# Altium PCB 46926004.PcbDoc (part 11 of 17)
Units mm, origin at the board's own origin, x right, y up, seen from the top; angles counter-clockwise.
Board outline 250 x 200 mm, 6 copper layers (Top Layer, INT1_GND, INT2_SIG, INT3_SIG, INT4_GND, Bottom Layer), stack 1.71 mm thick; 1450 components, 1293 nets, 5656 pads, 2307 vias.
Unrouted connection lines stored in the file: 2.
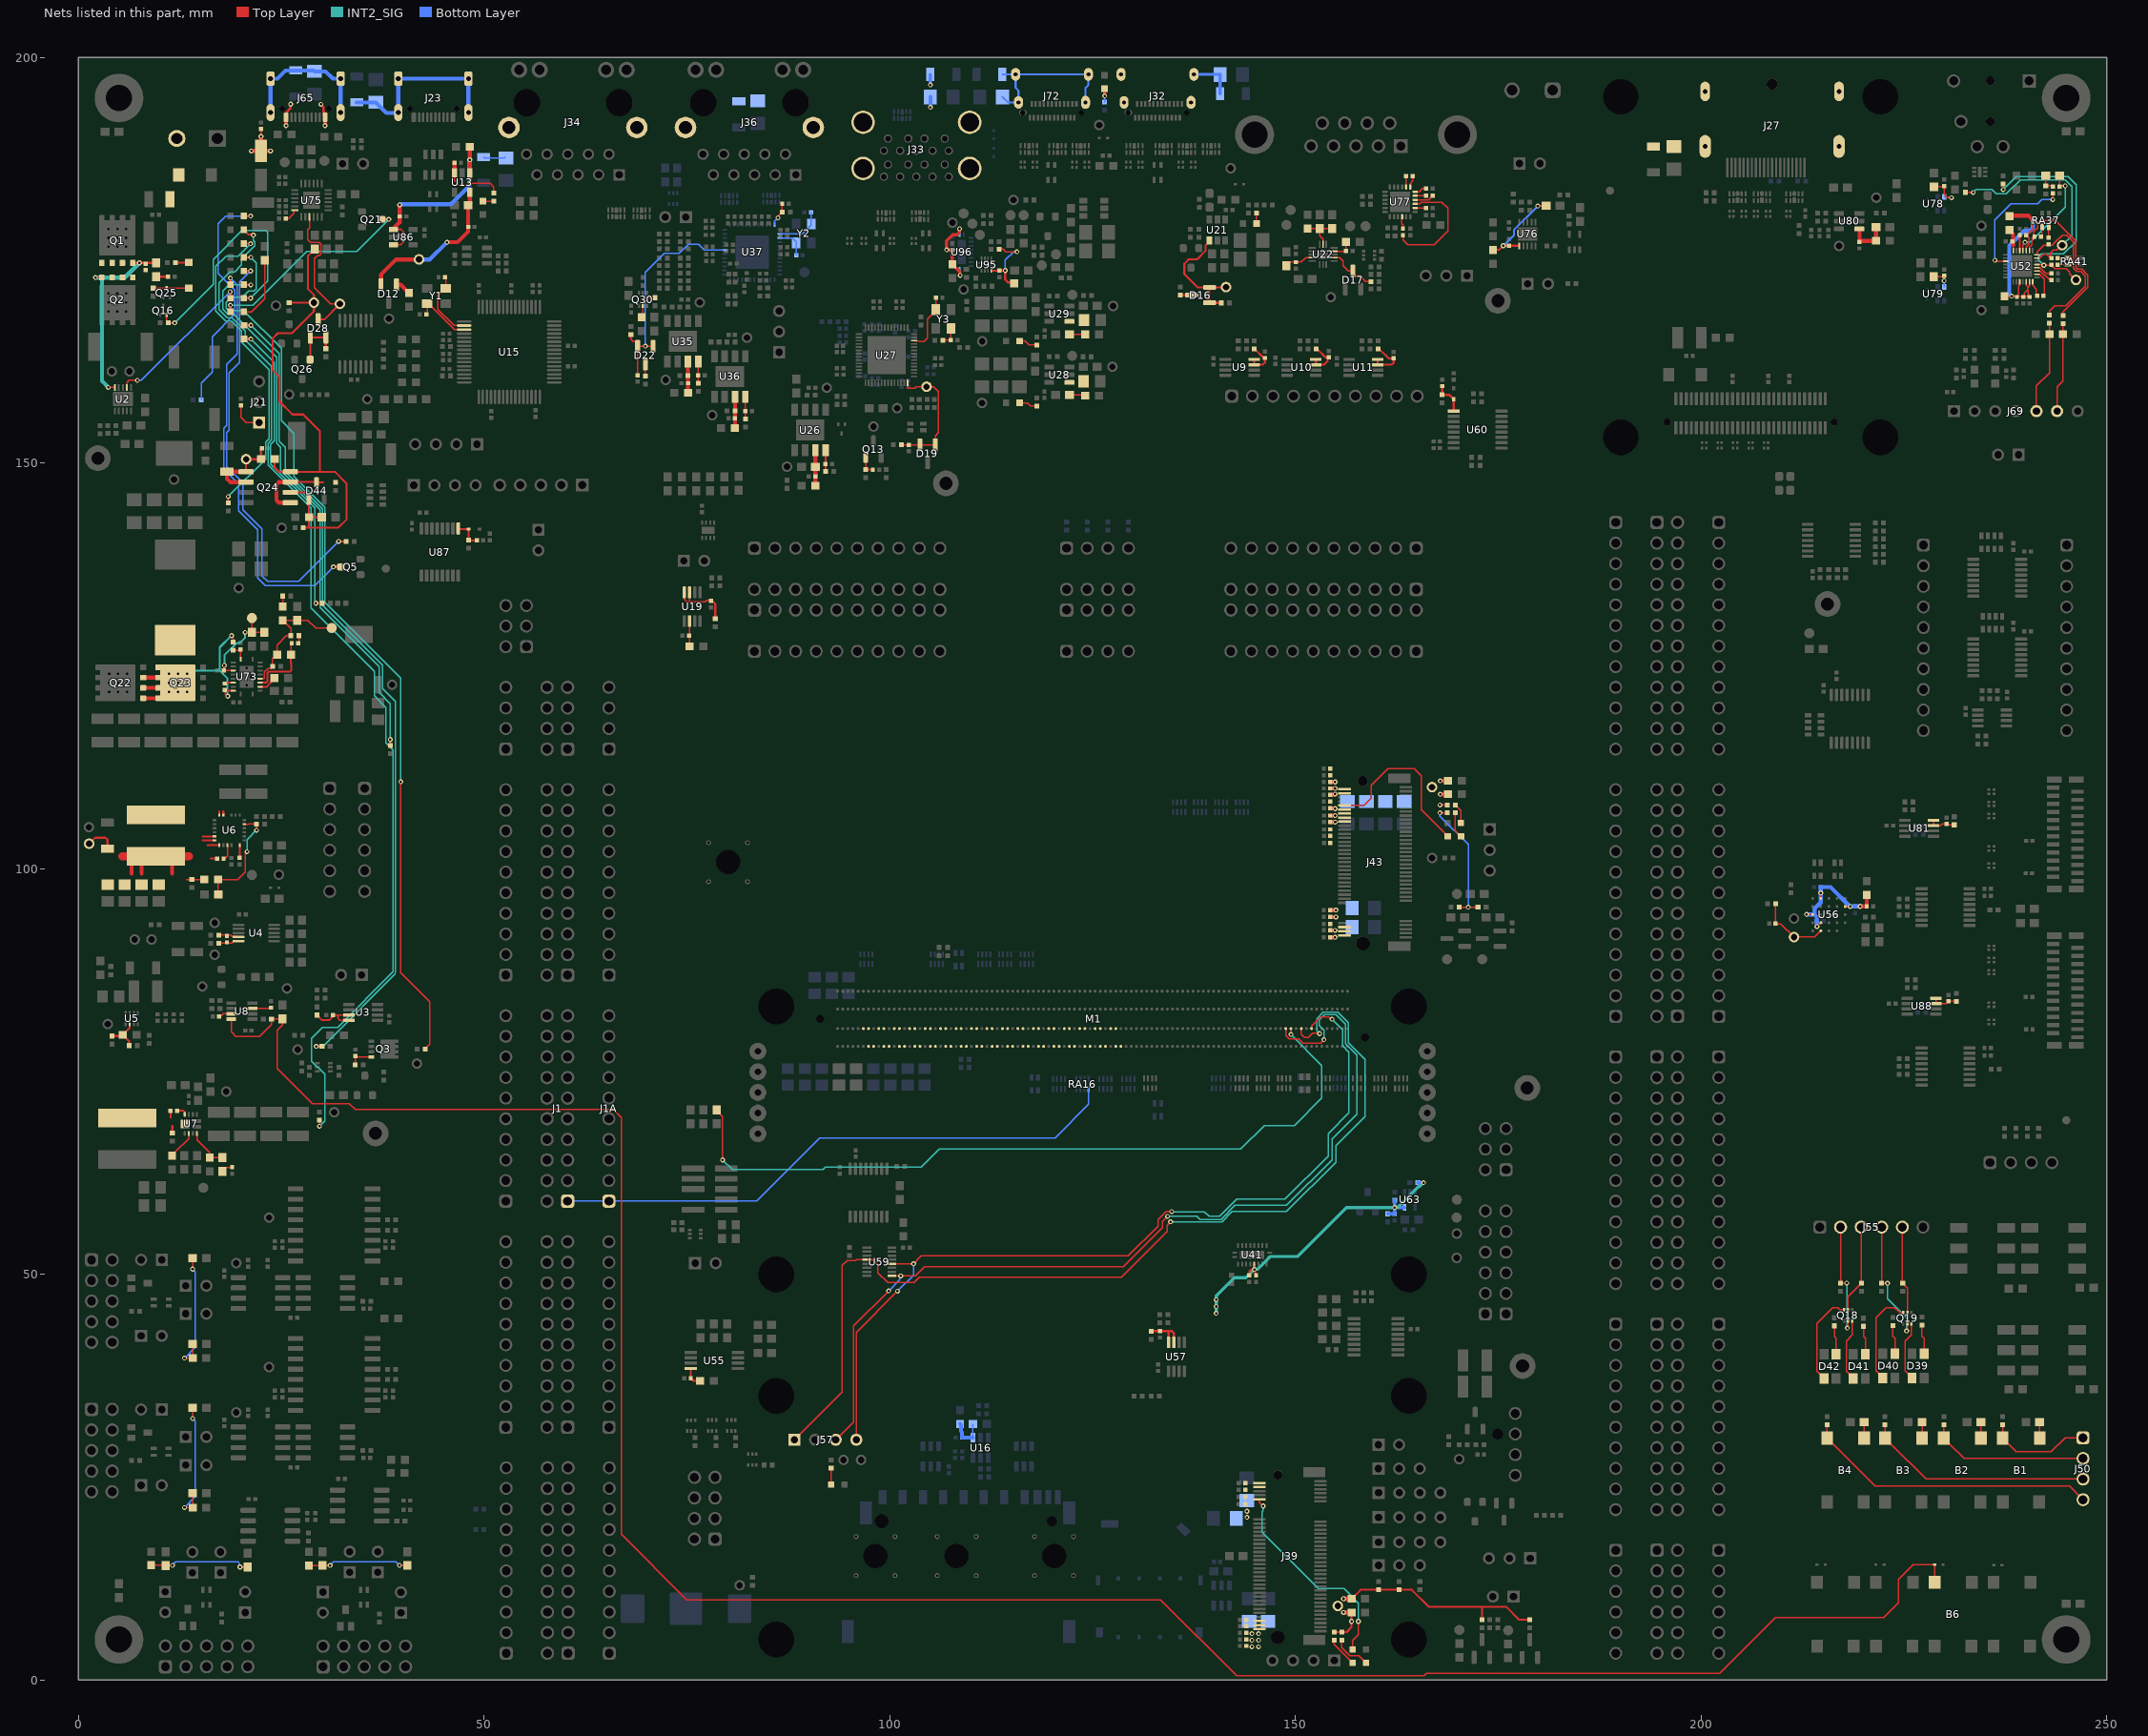
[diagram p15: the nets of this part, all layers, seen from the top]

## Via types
v1: diameter 0.6, hole 0.3, Top Layer to Bottom Layer, tented both sides, 2171 vias
v2: diameter 0.6, hole 0.3, Top Layer to Bottom Layer, 48 vias
v3: diameter 1, hole 0.5, Top Layer to Bottom Layer, tented both sides, 37 vias
v4: diameter 0.5, hole 0.2, Top Layer to Bottom Layer, tented both sides, 34 vias
v5: diameter 0.6, hole 0.3, Top Layer to Bottom Layer, tented bottom, 17 vias

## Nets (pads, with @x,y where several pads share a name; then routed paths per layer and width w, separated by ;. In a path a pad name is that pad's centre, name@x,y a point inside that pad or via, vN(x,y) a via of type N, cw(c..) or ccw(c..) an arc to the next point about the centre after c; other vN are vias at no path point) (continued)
JTAG_1_TDI: J57.4 M1.C08 U59.12 | length 107.1
  Top Layer w0.15: J57.4@95.88,29.62 95.88,42.841 v1(100.958,47.919) ; U59.12@100.263,51.3 100.269,51.306 102.932,51.306 v1(102.939,51.313) 103.898,52.272 129.389,52.272 133.063,55.946 133.063,56.758 134.052,57.748 v1(134.752,57.748) ; M1.C08@151.987,80.3 151.987,80.636 153.104,81.753 154.092,81.753 154.392,81.453 v1(154.514,81.453)
  INT2_SIG w0.15: v1(134.752,57.748) 134.787,57.712 138.788,57.712 139.346,57.154 140.654,57.154 142.785,59.285 148.732,59.285 154.034,64.587 154.034,67.324 156.6,69.89 156.6,77.4 155.797,78.203 155.797,80.17 v1(154.514,81.453)
  Bottom Layer w0.15: v1(100.958,47.919) 102.939,49.9 v1(102.939,51.313)
JTAG_1_TDO: J57.1 M1.C10 U59.4 | length 123
  Top Layer w0.15: J57.1@88.26,29.62 94.143,35.503 94.143,51.105 94.743,51.704 95.81,51.704 95.905,51.8 U59.4@97.187,51.8 97.914,51.8 98.535,51.179 98.535,50.204 99.738,49 103,49 103.65,49.65 128.581,49.65 134.195,55.264 134.195,56.071 v1(134.602,56.477) ; M1.C10@150.717,80.3 150.717,79.618 151.11,79.225 151.585,79.225 152.109,79.749 152.91,79.749 v1(152.989,79.67)
  INT2_SIG w0.15: v1(134.602,56.477) 140.932,56.477 142.202,57.748 148.898,57.748 154.982,63.832 154.982,65.891 158.56,69.469 158.56,76.482 156.5,78.542 156.5,81.017 155.217,82.3 153.434,82.3 152.635,81.501 152.635,80.024 v1(152.989,79.67)
JTAG_1_TMS: J57.3 M1.C13 U59.9 | length 115.8
  Top Layer w0.15: J57.3@93.34,29.62 95.533,31.812 95.533,43.629 v1(99.864,47.961) ; U59.9@100.263,49.8 v1(101.347,49.8) 103.155,49.8 104.305,50.95 128.793,50.95 133.63,55.787 133.63,56.526 v1(134.247,57.142) ; M1.C13@148.812,80.3 148.812,79.451 149.01,79.253 149.014,79.253 149.23,79.038 150.425,79.038 150.938,78.524 153.099,78.524 v1(153.5,78.925)
  INT2_SIG w0.15: v1(134.247,57.142) 137.862,57.142 138.227,56.777 140.808,56.777 142.53,58.5 148.894,58.5 154.514,64.119 154.514,66.66 157.6,69.746 157.6,77.018 156.159,78.459 156.159,80.83 154.989,82 153.558,82 152.935,81.377 152.935,80.659 153.514,80.08 153.514,78.939 v1(153.5,78.925)
  Bottom Layer w0.15: v1(99.864,47.961) 101.261,49.357 101.261,49.714 v1(101.347,49.8)
JTAG_1_VREF: M1.C12 R287.2 | length 94.6
  Top Layer w0.15: R287.2@78.65,70.25 78.65,70.2 79.375,69.475 79.375,64.11 v1(79.385,64.1) ; v1(149.447,79.563) M1.C12@149.447,80.3
  INT2_SIG w0.15: v1(79.385,64.1) 80.585,62.9 91.75,62.9 92.05,63.2 103.889,63.2 106.138,65.449 143.267,65.449 146.153,68.336 149.86,68.336 153.247,71.722 153.247,75.333 153.247,75.763 v1(149.447,79.563)
LED1: J55.5 Q19.2 R275.2 | length 10.8
  Top Layer w0.15: J55.5@224.805,55.825 224.805,48.945 R275.2@224.85,48.9 225.425,48.325 Q19.2@225.425,45.275
LED2: J55.4 Q19.5 R276.2 | length 15.4
  Top Layer w0.15: J55.4@222.265,55.825 222.265,48.915 R276.2@222.25,48.9 v1(222.975,48.9) ; v1(225.328,43.026) 225.328,43.147 225.425,43.245 Q19.5@225.425,43.925
  INT2_SIG w0.15: v1(222.975,48.9) 222.975,47 225.328,44.647 v1(225.328,43.026)
LED3: J55.3 Q18.2 R277.2 | length 10.9
  Top Layer w0.15: Q18.2@218.11,45.625 218.11,47.26 R277.2@219.75,48.9 219.725,48.925 J55.3@219.725,55.825
LED4: J55.2 Q18.5 R278.2 | length 14.2
  Top Layer w0.15: J55.2@217.185,55.825 217.185,48.915 R278.2@217.2,48.9 217.225,48.925 v1(217.95,48.925) ; v1(218.013,43.376) 218.013,43.497 218.11,43.595 Q18.5@218.11,44.275
  INT2_SIG w0.15: v1(217.95,48.925) 217.981,48.894 217.981,43.407 v1(218.013,43.376)
LINEOUTL: C333.2 L43.1 U52.16 | length 18.6
  Top Layer w0.15: U52.16@241.396,175.675 241.396,176.021 242.25,176.875 243.271,176.875 243.586,177.189 243.589,177.192 244.521,178.075 ; L43.1@242.925,168.225 242.925,168.75 243.575,169.4 244.951,169.4 247.35,171.799 247.35,173.05 246.8,173.6 246.293,173.6 245.885,174.008 245.885,177.24 245.05,178.075 244.521,178.075
LINEOUTL_CONN: C341.2 J69.5 L43.2 | length 11.5
  Top Layer w0.15: J69.5@241.33,156.4 241.33,159.505 242.925,161.1 C341.2@242.925,165.9 L43.2@242.925,167.225
LINEOUTR: C326.2 L45.1 U52.18 | length 21.1
  Top Layer w0.15: U52.18@240.471,176.2 240.481,176.21 240.481,176.619 240.775,176.913 240.775,177.75 240.95,177.925 241,177.925 241,178.526 241.45,178.976 241.45,179.55 241.825,179.925 243.624,179.925 246.185,177.364 246.185,174.132 246.417,173.9 246.924,173.9 247.65,173.174 247.65,171.675 244.6,168.625 L45.1@244.6,168.175
LINEOUTR_CONN: C338.2 J69.6 L45.2 | length 11.1
  Top Layer w0.15: J69.6@243.87,156.4 243.87,159.395 244.6,160.125 C338.2@244.6,165.9 L45.2@244.6,167.175
M2B_3V3: C192.2 C193.2 C194.2 C195.2 C196.1 C286.1 C358.2 C361.2 C362.2 C363.2 C364.2 C365.2 C366.2 C367.2 C368.2 C369.2 J39.2 J39.4 J39.70 J39.72 J39.74 L46.2 L47.2 R181.2 R184.1 R186.2 R187.2 R188.2 R195.1 R196.2 R197.2 R322.1 U41.6 U63.5 X63.1 | length 72.3
  Top Layer w0.25: C286.1@144.321,49.885 144.321,50.383 144.502,50.564 144.762,50.564 144.795,50.598 v1(144.923,50.598) ; U41.6@144.923,51.25 v1(144.923,50.598) ; C196.1@145.156,49.885 145.021,50.02 145.021,50.405 144.923,50.503 v1(144.923,50.598) ; R197.2@154.78,5.905 156.308,5.905 156.906,6.503 v1(156.906,7.222) L46.2@156.906,8.322 L46.2@156.904,8.319 ; L47.2@156.906,10.022 156.931,10.022 158.035,11.125 R196.2@160.25,11.125 R195.1@162.79,11.125 164.33,11.125 166.417,9.038 172.987,9.038 ; R184.1@172.987,7.423 172.987,9.038 ; R322.1@178.9,7.428 177.562,7.428 175.952,9.038 172.987,9.038
  Top Layer w0.6: v1(155.934,8.319) L46.2@156.904,8.319 ; v1(155.934,10.019) L47.2@156.904,10.019
  INT2_SIG w0.4: v1(140.228,45.2) v1(140.228,46.033) v1(140.228,46.867) v1(140.228,46.867) 140.229,47.339 142.475,49.585 143.911,49.585 144.962,50.636 145.338,50.636 146.902,52.2 150.25,52.2 156.298,58.248 v1(162.231,58.248) 162.269,58.286 162.629,58.286 165.141,60.798 165.25,60.798 165.739,61.287 v1(165.794,61.287)
  Bottom Layer w0.4: R186.2@161.364,57.459 C358.2@162.232,57.459 v1(162.231,58.248) v1(162.231,58.248) ; R181.2@162.231,59.148 v1(162.231,58.248) ; U63.5@163.45,58.248 v1(162.231,58.248) ; R188.2@165.1,61.321 165.117,61.304 165.777,61.304 v1(165.794,61.287)
  other v1: 144.637,4.09 145.452,4.089 144.638,4.905 145.453,4.904 144.639,5.72 145.454,5.719 144.017,20.05 144.017,20.8
M2M_3V3: C200.2 C201.2 C202.2 C203.2 C370.2 C371.2 C372.2 C373.2 C374.2 C375.2 C376.2 C377.2 C378.2 C379.2 C380.2 C381.2 C382.2 C383.2 C384.2 C385.2 C386.2 C387.2 C388.2 J43.2 J43.4 J43.12 J43.14 J43.16 J43.18 J43.70 J43.72 J43.74 L48.2 L49.2 R200.2 R202.2 R204.2 R417.1 X68.1 | length 25.4
  Top Layer w0.15: v1(167.816,106.9) R204.2@168.7,106.9 ; v1(167.816,107.862) R202.2@168.694,107.862 ; R417.1@170.166,95.27 170.171,95.265 v1(171.298,95.265) 172.491,95.265 R200.2@172.496,95.27
  Top Layer w0.5: C377.2@154.293,94.049 v1(154.989,94.049) ; C375.2@154.293,94.896 v1(154.989,94.896) ; C202.2@154.293,109.084 154.303,109.094 154.767,109.094 154.875,109.201 v1(154.902,109.201) ; C201.2@154.293,109.9 v1(154.896,109.9) ; C200.2@154.293,110.693 v1(154.896,110.693) ; C382.2@154.297,91.55 v1(154.9,91.55) ; C381.2@154.297,92.4 v1(154.9,92.4) ; C387.2@154.3,105.75 v1(154.903,105.75) ; C386.2@154.3,106.55 v1(154.903,106.55) ; C385.2@154.3,107.45 154.31,107.44 154.836,107.44 154.869,107.408 v1(154.896,107.408) ; v1(167.853,109.179) L48.2@168.828,109.179 ; v1(167.853,110.829) L49.2@168.828,110.829
  Bottom Layer w0.15: v1(167.816,106.9) 167.816,106.459 171.298,102.977 v1(171.298,95.265)
MSP_1_RX_N: M1.C47
MSP_1_RX_P: M1.C46
MSP_1_TX_N: M1.D46
MSP_1_TX_P: M1.D45
MSP_2_RX_N: M1.C50
MSP_2_RX_P: M1.C49
MSP_2_TX_N: M1.D49
MSP_2_TX_P: M1.D48
MSP_3_RX_N: M1.C53
MSP_3_RX_P: M1.C52
MSP_3_TX_N: M1.D52
MSP_3_TX_P: M1.D51
MSP_4_RX_N: M1.C56
MSP_4_RX_P: M1.C55
MSP_4_TX_N: M1.D55
MSP_4_TX_P: M1.D54
MSP_5_RX_N: M1.C59
MSP_5_RX_P: M1.C58
MSP_5_TX_N: M1.D58
MSP_5_TX_P: M1.D57
MSP_6_RX_N: M1.C62
MSP_6_RX_P: M1.C61
MSP_6_TX_N: M1.D61
MSP_6_TX_P: M1.D60
MSP_7_RX_N: M1.C65
MSP_7_RX_P: M1.C64
MSP_7_TX_N: M1.D64
MSP_7_TX_P: M1.D63
MSP_8_RX_N: M1.C68
MSP_8_RX_P: M1.C67
MSP_8_TX_N: M1.D67
MSP_8_TX_P: M1.D66
MSP_9_RX_N: M1.C71
MSP_9_RX_P: M1.C70
MSP_9_TX_N: M1.D70
MSP_9_TX_P: M1.D69
MSP_10_RX_N: M1.C74
MSP_10_RX_P: M1.C73
MSP_10_TX_N: M1.D73
MSP_10_TX_P: M1.D72
MSP_11_RX_N: M1.C77
MSP_11_RX_P: M1.C76
MSP_11_TX_N: M1.D76
MSP_11_TX_P: M1.D75
MSP_12_RX_N: M1.C80
MSP_12_RX_P: M1.C79
MSP_12_TX_N: M1.D79
MSP_12_TX_P: M1.D78
MSP_13_RX_N: M1.C83
MSP_13_RX_P: M1.C82
MSP_13_TX_N: M1.D82
MSP_13_TX_P: M1.D81
MSP_14_RX_N: M1.C86
MSP_14_RX_P: M1.C85
MSP_14_TX_N: M1.D85
MSP_14_TX_P: M1.D84
MSP_15_RX_N: M1.C89
MSP_15_RX_P: M1.C88
MSP_15_TX_N: M1.D88
MSP_15_TX_P: M1.D87
MSP_16_RX_N: M1.C92
MSP_16_RX_P: M1.C91
MSP_16_TX_N: M1.D91
MSP_16_TX_P: M1.D90
MSP_17_RX_N: M1.C95
MSP_17_RX_P: M1.C94
MSP_17_TX_N: M1.D94
MSP_17_TX_P: M1.D93
NetB1_1: B1.1 R240.2 | length 2
  Top Layer w0.15: B1.1@241.734,29.812 R240.2@241.734,31.811
NetB1_3: B1.3 J50.1 R241.2 | length 13
  Top Layer w0.15: R241.2@237.162,31.464 B1.3@237.162,29.812 237.162,29.736 237.811,29.087 237.887,29.087 238.848,28.126 243.151,28.126 244.875,29.85 J50.1@247.075,29.85
NetB2_1: B2.1 R242.2 | length 2
  Top Layer w0.15: B2.1@234.484,29.812 R242.2@234.484,31.811
NetB2_3: B2.3 J50.2 R243.2 | length 19.9
  Top Layer w0.15: R243.2@229.912,31.464 B2.3@229.912,29.812 229.912,29.736 230.561,29.087 230.637,29.087 232.414,27.31 J50.2@247.075,27.31
NetB3_1: B3.1 R244.2 | length 2
  Top Layer w0.15: B3.1@227.234,29.812 R244.2@227.234,31.811
NetB3_3: B3.3 J50.3 R245.2 | length 28.2
  Top Layer w0.15: R245.2@222.662,31.464 B3.3@222.662,29.812 222.662,29.736 223.311,29.087 223.387,29.087 227.704,24.77 J50.3@247.075,24.77
NetB4_1: B4.1 R246.2 | length 2
  Top Layer w0.15: B4.1@220.109,29.812 R246.2@220.109,31.811
NetB4_3: B4.3 J50.4 R247.2 | length 36.4
  Top Layer w0.15: R247.2@215.537,31.464 B4.3@215.537,29.812 215.537,29.736 216.186,29.087 216.262,29.087 221.443,23.906 245.399,23.906 J50.4@247.075,22.23
NetB6_3: B6.3 D15.2 R54.1 R55.1 U8.8 | length 290.7
  Top Layer w0.15: U8.8@18.835,81.475 18.835,79.89 19.4,79.325 22.325,79.325 23.8,80.8 R55.1@23.8,81.475 23.825,81.5 R54.1@25.175,81.5 25.175,80.723 24.51,80.058 24.51,75.377 28.837,71.05 33.385,71.05 34.135,70.3 65.904,70.3 66.9,69.304 66.9,18 75,9.9 133.4,9.9 142.75,0.55 165.837,0.55 166.137,0.85 202.274,0.85 209.137,7.713 222.513,7.713 224.3,9.5 224.3,12.375 226.15,14.225 228.75,14.225 228.789,14.186 B6.3@228.789,12.037
NetC5_1: C5.1 Q1.4 Q2.4 R7.2 U2.10 | length 24.5
  Top Layer w0.15: v1(3.684,159.334) U2.10@4.477,159.334
  Top Layer w0.25: v1(2.11,172.875) v1(2.11,172.875) 2.889,172.876 Q2.4@2.89,172.877 ; Q1.4@6.7,174.677 Q1.4@6.7,174.677 7.524,174.676 v1(7.525,174.675) 7.527,174.673 8.303,174.673 8.305,174.67 R7.2@9.55,174.67
  INT2_SIG w0.5: v1@2.091,172.856 2.907,172.856 ; v1(3.684,159.334) 2.898,160.12 2.898,172.847 2.907,172.856 ; v1(7.525,174.675) 5.706,172.856 2.907,172.856
NetC5_2: C5.2 Q1.1 Q1.2 Q1.3 Q2.1 Q2.2 Q2.3
NetC6_2: C6.2 R7.1 | length 1.4
  Top Layer w0.25: R7.1@9.55,172.97 C6.2@10.96,172.97
NetC7_1: C7.1 J21.1 | length 4
  Top Layer w0.15: C7.1@20.025,157.125 20.025,155.624 20.664,154.985 J21.1@22.26,154.985
NetC9_2: C9.2 R12.2 U3.7 U3.8 | length 6.4
  Top Layer w0.2: C9.2@31.377,81.975 31.987,81.975 ; U3.8@33.33,81.325 32.2,81.325 31.987,81.538 31.987,81.975 ; U3.7@33.33,81.975 31.987,81.975
  Top Layer w0.25: R12.2@29.413,81.965 30.043,81.335 30.894,81.335 31.377,81.818 C9.2@31.377,81.975
NetC10_1: C10.1 Q3.G R20.2 | length 3
  Top Layer w0.15: R20.2@34.125,75.8 34.125,76.8 Q3.G@36.125,76.8
NetC11_1: C11.1 R25.1 U4.9 | length 2.5
  Top Layer w0.15: R25.1@17.3,91.825 18.3,91.825 18.775,91.825 18.949,91.651 19.648,91.651 U4.9@19.725,91.574
NetC11_2: C11.2 R21.1 U4.10 | length 2.5
  Top Layer w0.15: R21.1@17.3,90.825 18.3,90.825 18.903,90.825 19.152,91.074 U4.10@19.725,91.074
NetC16_2: C16.2 R30.1 R31.2 U5.2 | length 4.7
  Top Layer w0.25: R31.2@4.128,79.375 5.313,79.375 C16.2@5.474,79.535 ; R30.1@6.248,78.2 6.248,78.761 C16.2@5.474,79.535 ; U5.2@6.325,80.847 6.325,80.387 C16.2@5.474,79.535
NetC27_2: C27.2 U6.22 | length 1.5
  Top Layer w0.25: C27.2@19.866,101.425 19.869,101.428 19.869,102.911 U6.22@19.871,102.913
NetC29_1: C29.1 L4.2 R37.2 U7.11 | length 1.8
  Top Layer w0.25: 11.35,69.325 11.355,69.33 C29.1@11.355,70.175 ; R37.2@11.575,67.4 11.575,68.316
NetC29_2: C29.2 U7.10 | length 1.3
  Top Layer w0.25: C29.2@12.155,70.175 12.927,70.175 13.109,69.992 U7.10@13.109,69.717
NetC30_2: C30.2 U7.2 | length 3.6
  Top Layer w0.15: C30.2@11.525,64.65 11.525,64.675 11.925,65.075 11.95,65.075 13.609,66.734 U7.2@13.609,67.367
NetC34_1: C34.1 L6.1 U6.10 U6.11 U6.16 U6.17 U6.18 | length 5.9
  Top Layer w0.25: 15.316,103.485 U6.17@16.793,103.485 ; 15.316,103.986 16.793,103.986 U6.16@16.795,103.988 ; 15.89,102.911 U6.18@17.367,102.911 ; 16.316,101.248 C34.1@16.989,101.248 ; U6.11@17.367,106.629 17.367,107.046 ; U6.10@17.867,106.629 17.867,107.046
NetC34_2: C34.2 U6.20 | length 1.8
  Top Layer w0.15: C34.2@17.991,101.25 18.041,101.25 18.37,101.579 U6.20@18.37,102.913
NetC36_2: C36.2 R44.1 | length 1.5
  Top Layer w0.15: R44.1@17.725,62.675 17.725,62.717 18.15,63.142 18.779,63.142 C36.2@18.954,63.317
NetC37_1: C37.1 R44.2 U7.4 | length 5.2
  Top Layer w0.15: U7.4@14.609,67.367 14.609,66.566 16.163,65.012 16.163,64.387 C37.1@16.175,64.375 R44.2@17.725,64.375
NetC38_1: C38.1 R46.1 R47.2 U6.5 | length 13.7
  Top Layer w0.15: R46.1@17.241,96.825 17.216,96.85 C38.1@17.216,98.675 19.641,98.675 20.541,99.575 20.541,101.85 v1(20.791,102.1) ; U6.5@20.445,105.489 20.926,105.489 20.938,105.5 R47.2@21.95,105.5 v1(21.95,104.75)
  INT2_SIG w0.15: v1(20.791,102.1) 20.791,103.591 v1@22.061,104.861
NetC38_2: C38.2 C42.2 C44.2 C45.2 C46.2 L6.2 R45.2 R51.1 X23.1 | length 18.7
  Top Layer w0.15: 13.251,98.675 R45.2@13.991,98.675 C38.2@15.516,98.675
  Top Layer w0.25: X23.1@1.327,103.076 2.076,103.825 3.337,103.825 3.582,103.581 R51.1@3.582,102.475
  Top Layer w0.5: 6.541,99.414 L6.2@6.541,100.892 ; 7.791,99.414 L6.2@7.791,100.892 ; 11.541,99.414 L6.2@11.541,100.892
  Top Layer w1: 5.416,101.55 L6.2@9.516,101.55 ; L6.2@9.541,101.525 L6.2@9.516,101.55 ; 13.616,101.55 L6.2@9.516,101.55
NetC39_1: C39.1 C72.1 L13.2 R83.2 U13.1 U13.3 U86.1 U86.3 | length 32.9
  Top Layer w0.15: U13.3@46.347,185.794 46.347,184.832 46.841,184.338 46.916,184.263 48.027,184.263 48.24,184.476 ; U13.1@48.241,185.788 48.24,184.476 ; R83.2@51.2,183.283 51.2,184.016 50.741,184.476 48.24,184.476
  Top Layer w0.2: U86.3@38.85,176.909 39.725,176.909 40.05,177.235 40.05,177.609 40.05,178.529 39.77,178.809 U86.1@38.85,178.809
  Top Layer w0.5: U86.1@38.77,178.85 39.6,179.68 C39.1@39.6,180.4 v1(39.6,181.828) ; U13.3@46.347,185.794 46.347,187.024 C72.1@46.353,187.03 ; U13.1@48.241,185.788 v1(48.241,187.39) L13.2@48.241,188.992
  Bottom Layer w0.5: v1(39.6,181.828) 39.659,181.888 45.897,181.888 48.241,184.231 v1(48.241,187.39)
NetC47_2: C47.2 U8.3 | length 2.3
  Top Layer w0.15: U8.3@21.465,82.775 C47.2@23.725,82.775
NetC49_2: C49.2 U8.7 | length 1.5
  Top Layer w0.15: C49.2@17.45,81.775 17.5,81.775 17.85,82.125 U8.7@18.835,82.125
NetC67_2: C67.2 R69.2 U9.7 U9.8 | length 4.4
  Top Layer w0.25: U9.8@144.9,162.775 U9.7@144.9,162.125 145.966,162.125 146.234,162.393 C67.2@146.234,162.955 146.099,162.955 144.994,164.059 R69.2@144.94,164.059
NetC68_2: C68.2 R70.2 U10.7 U10.8 | length 4.6
  Top Layer w0.25: U10.8@152.52,162.775 U10.7@152.52,162.125 153.516,162.125 153.961,162.57 153.961,162.884 C68.2@154.012,162.934 ; R70.2@152.56,164.059 152.683,164.059 153.723,163.02 153.973,163.02 C68.2@154.097,163.02
NetC70_2: C70.2 R77.2 U11.7 U11.8 | length 5.7
  Top Layer w0.25: U11.8@160.14,162.775 U11.7@160.14,162.125 161.881,162.125 162.1,162.344 C70.2@162.1,162.9 161.519,162.9 160.359,164.059 R77.2@160.18,164.059
NetC71_2: C71.2 J23.SH1 J23.SH2 J23.SH3 J23.SH4 R82.1 | length 22.7
  Bottom Layer w0.5: R82.1@34.3,194.46 C71.2@36.65,194.46 37.957,193.154 J23.SH2@39.43,193.154 ; J23.SH2@39.43,193.198 J23.SH4@39.43,197.377 J23.SH3@48.07,197.377 J23.SH1@48.07,193.198
NetC73_1: C73.1 D12.2 R84.1 U13.5 X29.1 | length 19.1
  Top Layer w0.25: D12.2@37.295,171.984 D12.2@37.298,171.987
  Top Layer w0.5: D12.2@37.298,171.987 37.298,173.235 39.162,175.099 X29.1@41.99,175.099 ; v1(45.43,177.224) 46.725,177.224 48.033,178.532 48.033,179.105 C73.1@48.037,179.109 R84.1@48.037,181.783 48.241,181.986 U13.5@48.241,183.388
  Bottom Layer w0.5: X29.1@41.99,175.099 43.305,175.099 v1(45.43,177.224)
NetC77_1: C77.1 U15.3 Y1.1 | length 7.2
  Top Layer w0.15: C77.1@42.99,168.325 Y1.1@42.99,169.675 43.115,169.675 46.34,166.45 U15.3@47.55,166.45
NetC81_1: C81.1 U15.2 Y1.3 | length 8.5
  Top Layer w0.15: C81.1@45.29,172.9 Y1.3@45.29,171.525 45.165,171.525 44.324,170.684 44.324,168.941 46.315,166.95 U15.2@47.55,166.95
NetC90_2: C90.2 L20.2 R96.1 U16.1 | length 4.8
  Bottom Layer w0.15: U16.1@110.25,29.88 R96.1@110.25,31.58
  Bottom Layer w0.5: L20.2@108.664,31.58 108.775,31.468 108.775,30.656 108.904,30.527 108.904,29.89 C90.2@108.914,29.88 U16.1@110.25,29.88
NetC92_2: C92.2 L21.2 U19.2 | length 3.1
  Top Layer w0.15: U19.2@75.325,130.535 75.325,128.78 75.35,128.755 L21.2@75.35,127.425
NetC93_2: C93.2 R100.2 U19.7 U19.8 | length 8.1
  Top Layer w0.15: U19.8@74.675,134.075 74.685,134.065 74.685,133.227 74.987,132.925 75.325,132.925 ; U19.7@75.325,134.075 75.325,132.925 ; C93.2@78.075,133.085 77.435,133.085 77.275,132.925 75.325,132.925
  Top Layer w0.25: C93.2@77.96,133.013 78.13,133.013 78.501,132.641 R100.2@78.501,130.798
NetC95_2: C95.2 R106.2 U22.4 | length 3.6
  Top Layer w0.15: R106.2@148.871,174.315 148.871,174.34 149.296,174.765 C95.2@150.071,174.765 150.725,174.765 151.275,175.315 U22.4@152.046,175.315
NetC97_2: C97.2 L26.2 U22.12 | length 2.6
  Top Layer w0.15: U22.12@154.746,176.115 156.238,176.115 C97.2@156.246,176.123 L26.2@156.246,177.265
NetC98_2: C98.2 Q30.5 R63.1 | length 3.7
  Top Layer w0.15: C98.2@69.441,167.96 69.576,168.095 Q30.5@69.576,169.389 69.576,169.929 70.036,170.389 R63.1@71.051,170.389
NetC101_2: C101.2 J32.SH1 J32.SH2 J32.SH3 J32.SH4 R120.1 | length 5.6
  Bottom Layer w0.4: J32.SH4@137.49,197.91 140.69,197.91 C101.2@140.7,197.9 R120.1@140.7,195.55
NetC104_2: C104.2 D19.1 D19.2 R122.2 U27.42 X42.1 | length 15.6
  Top Layer w0.15: R122.2@101.445,152.249 C104.2@102.375,152.249 D19.2@103.714,152.249 D19.1@105.614,152.249 105.614,153.333 106.02,153.738 106.02,158.786 105.395,159.411 X42.1@104.532,159.411 103.247,159.411 103.085,159.249 102.282,159.249 102.194,159.337 U27.42@102.194,159.891
NetC108_2: C108.2 L31.1 R124.1 U26.3 | length 5.6
  Top Layer w0.5: C108.2@90.823,148.359 R124.1@90.823,149.549 ; L31.1@90.826,147.186 90.826,151.576 90.823,151.578 U26.3@90.826,151.581
NetC110_2: C110.2 R123.1 U26.4 | length 5.3
  Top Layer w0.15: C110.2@92.096,149.866 U26.4@92.096,151.581
  Top Layer w0.25: C110.2@92.086,149.866 R123.1@92.085,148.95 92.085,151.57 U26.4@92.096,151.581
NetC126_1: C126.1 U27.54 Y3.3 | length 7.3
  Top Layer w0.15: U27.54@102.995,165.093 103.022,165.066 103.547,165.066 103.645,164.968 104.208,164.968 104.618,165.378 104.618,167.72 105.692,168.793 Y3.3@105.692,168.918 105.692,170.367 C126.1@105.695,170.37
NetC128_1: C128.1 R353.2 Y3.1 | length 2.5
  Top Layer w0.15: R353.2@106.561,165.138 C128.1@107.542,165.138 Y3.1@107.542,166.618
NetC129_1: C129.1 Q13.1 R137.2 | length 2.3
  Top Layer w0.2: Q13.1@97.046,150.674 R137.2@97.046,149.198 C129.1@97.911,149.198
NetC139_2: C139.2 L32.2 R138.2 U28.1 | length 2
  Top Layer w0.15: R138.2@122.154,158.4 123.993,158.4 L32.2@124.081,158.312
NetC140_2: C140.2 L33.2 R139.2 U29.1 | length 1.9
  Top Layer w0.15: R139.2@122.161,165.863 L33.2@124.1,165.863
NetC144_2: C144.2 R300.2 U78.5 | length 4.2
  Top Layer w0.15: R300.2@228.7,184.05 229.95,184.05 229.95,183.125 230.339,182.736 230.833,182.736 v1(230.864,182.705)
  Bottom Layer w0.15: U78.5@229.954,182.812 230.061,182.705 v1(230.864,182.705)
NetC148_2: C148.2 J34.S R148.1 | length 2.7
  Bottom Layer w0.18: R148.1@49.95,187.72 50.05,187.62 52.5,187.62 C148.2@52.6,187.72
NetC149_2: C149.2 L41.1 R165.1 U35.3 | length 3.8
  Top Layer w0.5: L41.1@75.12,158.66 75.122,158.663 75.122,162.501 U35.3@75.125,162.504
NetC150_2: C150.2 L42.1 R166.1 U36.3 | length 3.8
  Top Layer w0.5: L42.1@80.925,154.323 80.928,154.326 80.928,158.164 U36.3@80.93,158.167
NetC151_2: C151.2 R159.1 U35.4 | length 2.7
  Top Layer w0.15: R159.1@76.395,159.848 U35.4@76.395,162.504
NetC152_2: C152.2 R160.1 U36.4 | length 2.7
  Top Layer w0.15: R160.1@82.2,155.511 U36.4@82.2,158.167
NetC155_1: C155.1 D22.1 D22.2 R173.1 U37.43 | length 28
  Top Layer w0.15: R173.1@68.098,165.81 68.098,165.285 68.401,164.982 68.706,164.982 68.926,164.763 D22.2@68.926,164.404 ; C155.1@68.932,160.824 68.926,160.831 D22.2@68.926,164.404 ; D22.1@70.826,164.404 v1(69.876,164.404) D22.2@68.926,164.404
  Bottom Layer w0.15: v1(69.876,164.404) 69.876,173.505 72.198,175.827 74.014,175.827 75.181,176.994 76.413,176.994 77.135,176.272 78.47,176.272 78.473,176.275 79.142,176.275 79.167,176.25 U37.43@79.65,176.25
NetC159_1: C159.1 U37.15 Y2.3 | length 3.9
  Bottom Layer w0.15: U37.15@86.45,177.75 87.987,177.75 88.472,177.265 Y2.3@88.472,177.14 C159.1@88.472,175.63
NetC162_1: C162.1 U37.14 Y2.1 | length 5.9
  Bottom Layer w0.15: U37.14@86.45,178.25 89.257,178.25 90.322,179.315 Y2.1@90.322,179.44 90.322,180.878 C162.1@90.3,180.9
NetC177_1: C177.1 R176.2 U37.12 | length 2.9
  Top Layer w0.15: v1(86.225,180.225) 86.311,180.311 86.311,180.51 R176.2@86.751,180.95 C177.1@86.751,181.948
  Bottom Layer w0.15: U37.12@85.8,179.4 85.8,179.8 v1(86.225,180.225)
NetC182_2: C182.2 R340.2 U79.5 | length 2.6
  Top Layer w0.15: R340.2@228.675,172.975 229.95,172.975 229.954,172.971 v1(229.954,172.471)
  Bottom Layer w0.15: U79.5@229.954,171.696 v1(229.954,172.471)
NetC186_2: C186.2 J36.S R179.1
NetC215_1: C215.1 R205.1 R207.1 | length 12.9
  Top Layer w0.15: C215.1@8.961,14.134 10.632,14.134 R205.1@10.636,14.138 ; R205.1@10.641,14.134 v1(11.586,14.134) ; v1(19.915,13.93) 20.869,13.93 R207.1@21.082,14.142
  Bottom Layer w0.15: v1(11.586,14.134) 12.016,14.563 19.716,14.563 19.829,14.45 19.829,14.016 v1(19.915,13.93)
NetC216_1: C216.1 R206.1 R208.1 | length 12.5
  Top Layer w0.15: C216.1@28.4,14.121 30.071,14.121 R206.1@30.075,14.125 ; R206.1@30.079,14.121 v1(31.025,14.121) ; v1(39.575,14.129) R208.1@40.521,14.129
  Bottom Layer w0.15: v1(31.025,14.121) 31.454,14.55 39.154,14.55 v1(39.575,14.129)
NetC217_2: C217.2 C218.2 C219.2 C221.2 L60.2 L61.1 U52.4 U52.6 U52.7 U52.19 | length 27.1
  Top Layer w0.15: U52.19@240.071,176.2 240.081,176.21 240.081,176.643 240.446,177.008 240.446,177.704 240.125,178.025 240.075,178.025 240.9,178.85 v1(240.9,179.81)
  Top Layer w0.2: L60.2@237.55,170.55 237.575,170.575 v1(238.275,170.575) C218.2@238.925,170.575 ; U52.4@239.271,172.35 239.271,171.924 239.13,171.783 239.13,170.83 238.925,170.625 C218.2@238.925,170.575 ; U52.6@240.071,172.35 240.071,171.941 240.23,171.783 240.23,171.607 ; 240.305,171.327 240.305,170.892 240.325,170.872 240.325,170.725 240.475,170.575 C219.2@239.7,170.575 ; U52.7@240.471,172.35 240.471,171.849 240.23,171.607 ; C218.2@238.925,170.575 C219.2@239.7,170.575 ; C219.2@239.7,170.575 239.85,170.725 239.85,170.947 240.23,171.327 240.23,171.607
  Top Layer w0.5: L61.1@238.015,180.41 238.11,180.505 240.345,180.505 240.881,179.969 240.881,179.829 v1(240.9,179.81)
  Bottom Layer w0.5: v1(238.275,170.575) 237.987,170.863 237.987,176.787 239.815,178.615 240.539,178.615 240.9,178.976 v1(240.9,179.81)
NetC220_2: C220.2 L61.2 U52.23 | length 2.7
  Top Layer w0.2: U52.23@238.471,176.2 238.471,176.88
  Top Layer w0.5: L61.2@238.015,178.71 238.015,178.685 238.465,178.235 238.465,177.335 238.465,176.887 238.471,176.88
NetC222_2: C222.2 U52.21 | length 1.8
  Top Layer w0.2: U52.21@239.274,176.203 C222.2@239.274,177.974
NetC223_1: C223.1 RA41.3 | length 1.1
  Top Layer w0.15: C223.1@244.06,175.275 RA41.3@245.21,175.275
NetC223_2: C223.2 L11.1 U52.15 X71.1 | length 26.8
  Top Layer w0.15: L11.1@232.575,183.375 233.5,183.375 v1(233.525,183.35) ; U52.15@241.396,175.275 241.666,175.275 241.741,175.35 241.787,175.35 242.187,175.75 242.585,175.75 243.06,175.275 243.06,175.885 243.433,176.258 243.855,176.258 244.447,176.85 X71.1@244.5,176.85
  INT2_SIG w0.15: v1(233.525,183.35) 233.875,183.7 235.85,183.7 236.375,183.175 237.625,183.175 239.375,184.925 244.875,184.925 245.7,184.1 245.7,178.05 X71.1@244.5,176.85
NetC224_1: C224.1 RA41.4 | length 1.2
  Top Layer w0.15: C224.1@244.06,174.45 245.185,174.45 RA41.4@245.21,174.475
NetC224_2: C224.2 L10.1 U52.13 X72.1 | length 30.3
  Top Layer w0.15: v1(237.225,183.7) L10.1@237.225,184.4 ; U52.13@241.396,174.475 241.406,174.465 242.165,174.465 v1(242.246,174.384) ; v1@242.25,174.425 242.291,174.384 242.994,174.384 243.06,174.45 243.11,174.45 243.6,173.961 245.007,173.961 245.433,173.534 245.433,173.342 X72.1@246.2,172.575
  INT2_SIG w0.15: v1(237.225,183.7) 238.85,185.325 245.225,185.325 246.225,184.325 246.225,177.338 244.662,175.775 241.925,175.775 241.525,175.375 241.525,175.105 v1(242.246,174.384)
NetC225_1: C225.1 U52.10 | length 3.2
  Top Layer w0.15: U52.10@241.396,173.275 241.666,173.275 241.741,173.2 241.787,173.2 242.3,172.687 C225.1@242.3,170.6
NetC225_2: C225.2 U52.8 | length 1.9
  Top Layer w0.15: U52.8@240.871,172.35 240.871,171.888 241.3,171.46 C225.2@241.3,170.6
NetC226_2: C226.2 U52.12 | length 2
  Top Layer w0.15: U52.12@241.396,174.075 241.406,174.065 241.792,174.065 242.457,173.4 C226.2@243.075,173.4
NetC227_2: C227.2 U52.11 | length 2.1
  Top Layer w0.15: U52.11@241.396,173.675 241.666,173.675 241.741,173.6 241.833,173.6 242.333,173.1 242.5,173.1 243.025,172.575 C227.2@243.075,172.575
NetC229_2: C229.2 R231.2 U56.A4 X74.1 | length 9
  Top Layer w0.15: R231.2@209.185,95.7 C229.2@209.185,93.226 209.211,93.2 209.828,93.2 X74.1@211.453,91.575 213.975,91.575 U56.A4@214.75,92.35
NetC230_2: C230.2 C231.2 C232.2 C360.2 L62.1 U56.B4 U56.C5 U56.D1 U56.E4 | length 17.1
  Top Layer w0.15: v1(212.995,94.37) 213.005,94.36 213.74,94.36 U56.C5@213.75,94.35
  Top Layer w0.25: v1(214.275,92.875) U56.B4@214.75,93.35 ; U56.E4@214.75,96.35 v1(214.75,97.025) ; U56.D1@217.75,95.35 v1(218.375,95.35)
  Top Layer w0.5: v1@219.625,95.35 C230.2@220.413,95.35 L62.1@220.413,96.783
  Bottom Layer w0.5: v1(212.995,94.37) 213.972,94.37 ; v1(214.275,92.875) C231.2@214.275,93.53 214.265,93.54 214.265,94.077 213.972,94.37 ; C232.2@214.745,97.74 C232.2@214.748,97.74 ; v1@218.328,95.35 215.938,97.74 C232.2@214.748,97.74 ; v1(218.375,95.35) 218.38,95.355 C360.2@218.995,95.355 ; C360.2@219,95.36 C360.2@218.995,95.355 ; v1@219.61,95.355 C360.2@218.995,95.355 ; 213.972,94.37 213.972,95.057 214.75,95.835 v1(214.75,97.025) 214.748,97.028 C232.2@214.748,97.74
  other v1: 219.615,95.36
NetC233_2: C233.2 L63.2 U55.8 | length 2.6
  Top Layer w0.25: C233.2@75.475,37.215 75.825,36.865 L63.2@76.595,36.865 ; U55.8@75.475,38.4 75.475,37.175 C233.2@75.525,37.125
NetC235_2: C235.2 R248.2 U57.7 U57.8 | length 5.4
  Top Layer w0.3: R248.2@132.236,42.983 133.293,42.983 133.335,43.025 134.302,43.025 134.303,43.023 134.352,43.023 ; U57.8@134.352,41.66 134.352,43.023 ; 134.352,43.025 134.352,43.023 ; U57.7@135.002,41.66 135.002,42.773 134.752,43.023 134.352,43.023
NetC263_1: C263.1 R293.1 R294.1 | length 15.8
  Top Layer w0.15: v1(13.075,39.667) C263.1@14.075,39.667 R293.1@14.075,41.442 ; v1(14.075,50.642) R294.1@14.075,51.967
  Bottom Layer w0.15: v1(13.075,39.667) 14.425,41.017 14.425,50.292 v1(14.075,50.642)
NetC264_1: C264.1 R295.1 R296.1 | length 15.8
  Top Layer w0.15: v1(13.075,21.25) C264.1@14.075,21.25 R295.1@14.075,23.025 ; v1(14.075,32.225) R296.1@14.075,33.55
  Bottom Layer w0.15: v1(13.075,21.25) 14.425,22.6 14.425,31.875 v1(14.075,32.225)
NetC267_1: C267.1 R305.1 U73.11 | length 2
  Top Layer w0.15: R305.1@19.08,126.925 19.992,126.925 U73.11@19.992,125.825
NetC268_1: C268.1 C277.1 U73.4 | length 8.4
  Top Layer w0.15: C277.1@26.192,126.382 C268.1@26.192,127.773
  Top Layer w0.25: U73.4@22.392,122.925 23.138,122.925 23.299,123.086 23.299,124.131 23.445,124.277 26.071,124.277 26.256,124.463 26.256,125.315 26.192,125.379 C277.1@26.192,126.382
NetC268_2: C268.2 R306.2 | length 1
  Top Layer w0.15: C268.2@27.192,127.773 R306.2@27.192,128.725
NetC269_1: C269.1 U73.3 | length 2.3
  Top Layer w0.25: U73.3@22.392,122.425 23.203,122.425 23.738,122.96 23.738,123.127 24.113,123.502 C269.1@24.163,123.502
NetC271_2: C271.2 R310.1 R311.1 U73.14 X87.1 | length 11.2
  Top Layer w0.15: v1(18,125.06) 18,124.44 18.015,124.425 U73.14@19.092,124.425 ; v1(20.548,129.125) R311.1@21.392,129.125 ; X87.1@21.392,130.891 R311.1@21.392,129.125 ; R310.1@22.892,129.125 R311.1@21.392,129.125
  INT2_SIG w0.25: v1(18,125.06) 18,126.315 19.485,127.8 19.85,127.8 20.548,128.498 v1(20.548,129.125)
NetC276_1: C276.1 L9.1 Q22.1 Q22.2 Q22.3 Q23.5 Q23.6 Q23.7 Q23.8 R305.2 U73.19 | length 27.8
  Top Layer w0.15: v1(18.87,128.73) 18.87,128.644 19.08,128.434 R305.2@19.08,127.925
  Top Layer w0.25: Q23.5@9.812,124.825 9.85,124.825 10.488,124.187 10.825,124.187 Q23.8@10.892,124.12 ; v1(18.416,121.271) 18.362,121.271 18.133,121.5 18.133,121.832 18.04,121.925 U73.19@19.092,121.925
  Top Layer w0.5: Q22.1@7.975,121.015 9.812,121.015 9.9,121.102 10.238,121.102 10.865,121.73 Q23.8@10.892,121.73 ; Q22.2@7.975,122.285 9.812,122.285 9.9,122.372 10.313,122.372 10.865,122.925 Q23.8@10.892,122.925 ; Q22.3@7.975,123.555 9.812,123.555 11.572,123.555 Q23.8@12.207,122.92
  INT2_SIG w0.25: Q23.8@13.282,124.12 13.31,124.12 13.595,124.405 17.435,124.405 ; v1(18.416,121.271) 18.349,121.338 18.349,123.491 17.435,124.405 ; v1(18.87,128.73) 17.425,127.285 17.425,124.415 17.435,124.405
NetC276_2: C276.2 U73.17 | length 1.2
  Top Layer w0.25: C276.2@17.942,122.925 U73.17@19.092,122.925
NetC277_2: C277.2 C279.2 R306.1 R309.2 R312.1 U73.5 X89.1 | length 16.4
  Top Layer w0.15: U73.5@22.392,123.425 22.854,123.425 22.942,123.513 22.942,124.269 23.373,124.7 23.717,124.7 R312.1@23.942,124.925 23.942,125.882 24.442,126.382 C277.2@24.492,126.382 24.492,127.575 25.642,128.725 R306.1@26.192,128.725 26.192,129.604 25.196,130.6 C279.2@25.196,130.625 R309.2@26.992,130.625 28.275,130.625 29.245,129.655 31.205,129.655 X89.1@31.225,129.675
NetC279_1: C279.1 R318.2 | length 1.3
  Top Layer w0.15: C279.1@25.196,132.325 R318.2@25.196,133.605
NetC288_2: C288.2 J65.SH1 J65.SH2 J65.SH3 J65.SH4 R319.1 | length 17.8
  Bottom Layer w0.5: J65.SH2@23.68,193.197 J65.SH4@23.68,197.377 24.527,197.377 25.535,198.385 R319.1@26.775,198.385 28.99,198.385 C288.2@29.1,198.275 30.475,198.275 31.373,197.377 J65.SH3@32.32,197.377 J65.SH1@32.32,193.197
NetC289_2: C289.2 J65.A4/B9 J65.B4/A9 L77.1 | length 10.7
  Top Layer w0.15: v1(22.5,190.255) C289.2@22.5,191.075
  Top Layer w0.3: J65.B4/A9@25.6,192.622 25.7,192.722 25.7,193.298 26.132,193.729 26.132,194.197 v1(26.17,194.235) ; v1(29.9,194.225) 29.9,194.189 30.19,193.899 30.19,193.408 30.276,193.322 30.276,192.747 J65.A4/B9@30.4,192.622
  Top Layer w0.5: v1(21.315,188.475) L77.1@22.505,188.475 ; L77.1@22.495,188.47 v1(23.685,188.47) ; L77.1@22.5,188.465 v1(22.5,190.255) ; v1(25.6,191.6) J65.B4/A9@25.6,192.622 ; v1(30.4,191.6) J65.A4/B9@30.4,192.622
NetC298_2: C298.2 U75.24 | length 1.8
  Top Layer w0.15: C298.2@25.55,180.15 25.95,180.15 26.045,180.245 ; 25.97,180.17 26.045,180.245 ; U75.24@26.675,181.15 26.622,181.15 26.572,181.1 26.572,180.772 26.045,180.245
NetC299_2: C299.2 C300.2 D44.1 Q24.2 Q24.4 R316.1 R332.1 R336.1 R342.2 X95.1 | length 66.4
  Top Layer w0.25: C300.2@24.2,150.475 24.2,149.445 24.715,148.93 Q24.4@26.13,148.93 29.75,148.93 ; R316.1@25.975,169.775 X95.1@29.025,169.775 ; Q24.2@26.13,146.39 28.057,146.39 28.35,146.097 28.35,145.575 D44.1@28.4,145.525 ; R332.1@27.71,142.03 28.274,142.03 ; D44.1@28.41,145.515 C299.2@28.41,143.33 R336.1@30,143.33 ; C299.2@28.42,143.32 28.42,142.176 28.274,142.03 ; R342.2@29.125,176.375 28.31,175.56 28.31,171.445 29.025,170.73 X95.1@29.025,169.775 ; 28.274,142.03 32.04,142.03 33.03,143.02 33.03,147.505 31.605,148.93 29.75,148.93 ; X95.1@29.025,169.775 29.025,168.72 26.32,166.015 24.585,166.015 23.96,165.39 23.96,161.454 24.775,160.639 24.775,157.613 26.389,155.999 27.71,155.999 29.75,153.959 29.75,148.93
NetC300_1: C300.1 C301.2 F2.1 Q24.5 Q24.6 X96.1 | length 10.5
  Top Layer w0.25: F2.1@18.3,148.925 F2.1@18.305,148.93 ; Q24.5@20.669,148.93 20.675,148.935 X96.1@20.675,150.475 C300.1@22.5,150.475 C301.2@22.5,151.825
  Top Layer w0.5: F2.1@18.3,148.925 18.3,148.075 18.715,147.66 Q24.6@20.669,147.66 ; F2.1@18.305,148.93 Q24.5@20.669,148.93
NetC302_2: C302.2 L78.2 R346.2 U76.1 | length 11.2
  Top Layer w0.15: R346.2@180.875,181.685 R346.2@180.9,181.71
  Top Layer w0.25: L78.2@174.375,176.275 175.098,176.275 v1(175.613,176.79) C302.2@176.3,176.79 ; C302.2@176.294,176.783 U76.1@177.6,176.783 ; v1(179.875,181.685) R346.2@180.875,181.685
  Bottom Layer w0.25: v1(175.613,176.79) 175.638,176.79 176.958,178.11 176.958,178.768 v1(179.875,181.685)
NetC303_1: C303.1 U77.2 | length 1.5
  Top Layer w0.15: U77.2@163.65,184.025 U77.2@163.65,184.215 ; U77.2@163.651,184.026 C303.1@163.651,185.384
NetC303_2: C303.2 U77.1 | length 1.5
  Top Layer w0.15: U77.1@164.15,184.025 U77.1@164.15,184.215 164.15,184.455 164.45,184.755 C303.2@164.45,185.384
NetC305_1: C305.1 U77.23 | length 1.4
  Top Layer w0.15: U77.23@164.725,182.95 C305.1@166.1,182.95
NetC305_2: C305.2 U77.22 | length 2.4
  Top Layer w0.15: U77.22@164.725,182.45 166.438,182.45 166.715,182.727 166.715,182.765 C305.2@166.9,182.95
NetC307_1: C307.1 U77.16 | length 1.5
  Top Layer w0.15: U77.16@163.15,180.375 163.138,180.363 163.138,180.185 163.125,180.172 163.125,179.907 163.124,179.905 163.124,179.471 163.249,179.346 C307.1@163.249,178.9
NetC307_2: C307.2 U77.21 | length 14.3
  Top Layer w0.15: C307.2@163.249,178.1 163.249,177.496 163.84,176.905 167.097,176.905 168.78,178.588 168.78,181.41 168.04,182.15 165.519,182.15 165.319,181.95 U77.21@164.725,181.95
NetC309_1: C309.1 U77.24 | length 1.5
  Top Layer w0.15: U77.24@164.725,183.45 165.26,183.45 165.645,183.835 C309.1@166.1,183.835
NetC310_1: C310.1 U77.20 | length 1.4
  Top Layer w0.15: U77.20@164.725,181.45 C310.1@166.1,181.45
NetC314_2: C314.2 R363.2 U81.7 U81.8 | length 3.3
  Top Layer w0.15: U81.7@228.66,105.313 229.521,105.313 229.711,105.503 C314.2@230.233,105.503 230.335,105.4 R363.2@231.2,105.4 ; U81.7@228.66,105.315 U81.8@228.66,105.965
NetC320_2: C320.2 R371.2 U88.7 U88.8 | length 3.3
  Top Layer w0.15: U88.8@228.944,84.04 U88.7@228.944,83.39 230.21,83.39 C320.2@230.47,83.65 230.475,83.645 R371.2@231.44,83.645
NetC323_2: C323.2 L91.2 U96.1 U96.6 U96.10 | length 10
  Top Layer w0.4: v1(108.61,178.875) 108.589,178.855 108.589,178.423 108.29,178.123 107.743,178.123 107.01,177.39 v1(107.01,176.275) C323.2@107.71,176.275 107.71,174.486 107.985,174.211 108.01,174.211 108.632,173.589 108.632,173.168 v1(108.67,173.13)
  Bottom Layer w0.2: v1(107.01,176.275) U96.6@107.71,176.275 ; U96.1@108.61,173.875 108.61,173.19 v1(108.67,173.13) ; U96.10@108.61,178.175 v1(108.61,178.875)
NetC324_2: C324.2 L92.2 R387.2 U95.12 | length 9.6
  Top Layer w0.15: R387.2@113.495,176.361 113.971,176.361 114.288,176.044 v1(115.664,176.044)
  Top Layer w0.2: U95.12@112.516,173.711 C324.2@113.495,173.711 C324.2@113.497,173.709
  Top Layer w0.3: C324.2@113.497,173.709 113.511,173.723 114.232,173.723 v1(114.245,173.735) 114.245,172.617 114.601,172.261 115.364,172.261 L92.2@115.375,172.25
  Bottom Layer w0.15: v1(114.245,173.735) 114.245,175.003 115.254,176.012 115.632,176.012 v1(115.664,176.044)
NetC326_1: C326.1 RA37.3 | length 1.2
  Top Layer w0.15: C326.1@242,177.925 242,179.078 RA37.3@242.05,179.128
NetC327_1: C327.1 R216.2 U52.20 | length 12.4
  Top Layer w0.15: U52.20@239.671,176.2 239.671,176.912 239.921,177.161 v1(239.921,177.225) ; R216.2@244.175,185.45 244.175,184.175 244.183,184.167 v1(244.867,184.167)
  INT2_SIG w0.15: v1(239.921,177.225) 240.534,177.225 244.867,181.558 v1(244.867,184.167)
NetC329_2: C329.2 J72.SH1 J72.SH2 J72.SH3 J72.SH4 R397.1 | length 20.1
  Bottom Layer w0.25: C329.2@113.89,195.135 114.565,194.46 J72.SH2@115.87,194.46 115.87,195.905 115.51,196.265 J72.SH3@115.51,197.91 ; R397.1@113.89,197.91 J72.SH3@115.51,197.91 ; J72.SH1@124.13,194.46 124.13,196.255 124.49,196.615 J72.SH4@124.49,197.91 J72.SH3@115.51,197.91
NetC330_2: C330.2 J33.S1 J33.S2 J33.S3 J33.S4 R398.1 | length 2.6
  Bottom Layer w0.4: v1(105.01,196.615) R398.1@105.01,197.91
  Bottom Layer w0.5: v1(105.01,193.846) C330.2@105.01,195.135
NetC333_1: C333.1 RA37.4 | length 1.3
  Top Layer w0.15: C333.1@242.85,177.875 RA37.4@242.85,179.128
NetC334_1: C334.1 L12.1 R216.1 | length 2.2
  Top Layer w0.15: R216.1@242.475,185.45 L12.1@242.475,184.175 C334.1@243.35,184.175
NetC334_2: C334.2 U52.27 | length 15.3
  Top Layer w0.15: v1(236.2,175) 236.322,175 236.447,174.875 U52.27@237.546,174.875 ; v1(243.35,182.475) C334.2@243.35,183.175
  Bottom Layer w0.15: v1(236.2,175) 236.2,179.968 238.172,181.94 241.459,181.94 241.994,182.475 v1(243.35,182.475)
NetC346_2: C346.2 J27.S1 J27.S2 J27.S3 J27.S4 R267.1
NetC347_2: C347.2 L75.2 R439.1 U80.1 | length 5.2
  Top Layer w0.5: U80.1@219.525,178.847 219.525,177.367 219.55,177.392 L75.2@221.55,177.392 R439.1@221.55,179.092
NetC355_2: C355.2 R109.1 R110.1 U22.15 | length 5.1
  Top Layer w0.15: C355.2@151.496,178.89 R110.1@152.996,178.89 ; U22.15@153.396,176.965 153.396,177.615 152.996,178.015 R110.1@152.996,178.89 ; R109.1@154.546,178.89 R110.1@152.996,178.89
NetC391_1: C391.1 D10.1 R95.1 U87.9 | length 3.7
  Top Layer w0.25: U87.9@46.815,141.936 46.886,141.865 D10.1@48.09,141.865 48.09,140.476 48.075,140.461 C391.1@49.1,140.461
NetC393_1: C393.1 D13.1 R189.1 U60.9 | length 4.2
  Top Layer w0.3: C393.1@168.083,159.485 R189.1@168.083,158.41 168.965,158.41 D13.1@169.5,157.875 U60.9@169.5,156.405
NetD1_2: D1.2 F1.1 J17.2
NetD2_1: D2.1 Q16.2 R347.2 | length 29.8
  Top Layer w0.15: Q16.2@10.88,168.256 10.88,167.475 R347.2@11.075,167.28 v1(11.875,167.28)
  Top Layer w0.25: D2.1@20.4,170.325 v1(21.225,170.325)
  INT2_SIG w0.15: v1(11.875,167.28) 16.609,172.014 16.609,175.111 20.167,178.67 23.107,178.67 23.352,178.425 23.352,172.452 v1(21.225,170.325)
NetD2_2: D2.2 U2.7 | length 18.8
  Top Layer w0.15: U2.7@5.977,159.334 5.977,159.938 6.232,160.193 v1(7.281,160.193)
  Top Layer w0.25: v1(18.71,171.12) 18.71,170.365 D2.2@18.75,170.325
  Bottom Layer w0.15: v1(7.281,160.193) 7.783,160.193 v1(18.71,171.12)
NetD4_1: D4.1 R10.2 | length 29.5
  Top Layer w0.25: D4.1@20.4,180.45 v1(21.225,180.45)
  Bottom Layer w0.15: R10.2@15.145,157.775 15.145,159.88 16.495,161.23 16.495,165.595 19.263,168.363 19.263,171.33 17.21,173.382 17.21,179.51 18.15,180.45 v1(21.225,180.45)
NetD5_1: D5.1 R24.1 | length 113.2
  Top Layer w0.15: v1(39.736,110.704) 39.736,87.164 43.3,83.6 43.3,78.35 R24.1@42.725,77.775
  Top Layer w0.25: D5.1@20.4,175.35 v1(21.25,175.35)
  INT2_SIG w0.15: v1(21.25,175.35) 21.9,174.7 21.9,171.46 21.64,171.2 20.989,171.2 20.214,170.425 18.818,170.425 18.196,169.803 18.196,169.109 18.481,168.825 20.35,168.825 25.035,164.14 25.035,155.207 26.587,153.655 26.587,148.342 30.4,144.529 30.4,132.831 39.736,123.495 v1(39.736,110.704)
NetD6_1: D6.1 R40.1 | length 69.8
  Top Layer w0.15: R40.1@38.444,114.968 v1(38.444,115.921)
  Top Layer w0.25: D6.1@20.4,172 20.434,171.966 v1(21.259,171.966)
  INT2_SIG w0.15: v1(21.259,171.966) 18.566,171.966 17.8,171.2 17.8,168.99 18.394,168.396 19.087,168.396 24.426,163.057 24.426,152.465 24.94,151.952 24.94,149.094 29.8,144.234 29.8,132.173 37.049,124.924 37.049,121.748 38.444,120.353 v1(38.444,115.921)
NetD6_2: D6.2 Q5.3 | length 52.2
  Top Layer w0.25: v1(18.738,172.82) 18.738,172.012 D6.2@18.75,172 ; v1(31.439,137.2) Q5.3@32.364,137.2
  Bottom Layer w0.15: v1(18.738,172.82) 18.738,172.773 19.563,171.948 19.563,163.463 18.275,162.175 18.275,154.62 17.924,154.268 17.924,149.221 19.717,147.428 19.717,144.143 22.11,141.75 22.11,135.826 23.042,134.895 29.134,134.895 v1(31.439,137.2)
NetD7_1: D7.1 R52.1 | length 54.1
  Top Layer w0.25: D7.1@20.4,173.675 v1(21.225,173.675) ; v1(32.079,140.34) R52.1@33.004,140.34
  Bottom Layer w0.15: v1(21.225,173.675) 19.863,172.313 19.863,162.408 18.575,161.12 18.575,154.03 18.3,153.755 18.3,149.555 20.252,147.603 20.252,144.25 22.63,141.873 22.63,136.1 23.33,135.4 27.139,135.4 v1(32.079,140.34)
NetD9_1: D9.1 R60.2 | length 102.3
  Top Layer w0.15: v1(29.324,78.1) 30,78.1 R60.2@30.025,78.125
  Top Layer w0.25: D9.1@20.425,166.975 v1(21.25,166.975)
  INT2_SIG w0.15: v1(21.25,166.975) 24.726,163.499 24.726,152.721 25.495,151.952 25.495,148.963 30.1,144.358 30.1,132.497 37.5,125.097 37.5,122.235 39.1,120.635 39.1,87.165 39.009,87.073 39.009,86.987 30.122,78.1 v1(29.324,78.1)
NetD11_1: D11.1 R83.1 | length 1.4
  Top Layer w0.15: D11.1@49.84,182.278 51.196,182.278 R83.1@51.2,182.283
NetD12_1: D12.1 L15.2 | length 2
  Top Layer w0.5: D12.1@39.195,171.984 39.719,171.984 L15.2@40.755,170.947
NetD14_1: D14.1 R99.1 | length 2
  Top Layer w0.15: D14.1@92.775,24.1 R99.1@92.775,26.131
NetD16_1: D16.1 D16.2 R104.1 U21.4 X34.1 | length 15.2
  Top Layer w0.25: U21.4@139.42,177.436 139.42,177.286 138.908,176.774 138.908,176.124 137.919,175.136 136.871,175.136 136.306,174.571 136.306,173.294 137.947,171.653 D16.2@139.415,171.653 ; R104.1@140.87,169.742 140.865,169.747 139.42,169.747 D16.1@139.415,169.753 D16.2@139.415,171.653 ; X34.1@141.44,171.69 141.422,171.671 139.433,171.671 D16.2@139.415,171.653
NetD16_3: D16.3 R105.1 | length 1.4
  Top Layer w0.25: R105.1@135.815,170.703 D16.3@137.215,170.703
NetD17_3: D17.3 R117.2 U22.10 | length 6.3
  Top Layer w0.15: U22.10@154.746,175.315 155.445,175.315 155.846,174.914 155.846,174.315 156.496,173.665 D17.3@157.096,173.665 157.096,173.309 157.316,173.09 157.931,173.09 158.656,172.365 R117.2@159.296,172.365
NetD18_1: D18.1 R119.1 | length 1.3
  Top Layer w0.15: D18.1@145.195,179.521 R119.1@145.195,180.8
NetD20_1: D20.1 R144.1 | length 2.3
  Top Layer w0.15: D20.1@115.996,157.419 116.961,157.419 117.35,157.03 R144.1@118.129,157.03
NetD21_1: D21.1 R145.1 | length 2.3
  Top Layer w0.15: D21.1@115.996,165.043 116.676,165.043 117.159,164.559 R145.1@118.129,164.559
NetD22_3: D22.3 R400.1 | length 1.5
  Top Layer w0.15: R400.1@69.876,160.724 D22.3@69.876,162.204
NetD24_1: D24.1 R315.1 | length 8
  Top Layer w0.15: D24.1@20.4,168.65 21.354,168.65 22.995,170.291 R315.1@22.995,175.003
NetD24_2: D24.2 Q21.3 | length 25.6
  Top Layer w0.25: v1(18.738,169.466) 18.738,168.662 D24.2@18.75,168.65 ; Q21.3@37.355,180.045 v1(38.249,180.045)
  INT2_SIG w0.15: v1(18.738,169.466) 21.529,169.466 28.162,176.1 34.304,176.1 v1(38.249,180.045)
NetD25_1: D25.1 R187.1 | length 4.7
  Top Layer w0.15: R187.1@155.708,4.905 155.708,3.986 156.678,3.016 157.79,3.016 D25.1@158.7,2.105
NetD26_1: D26.1 R197.1 | length 3.7
  Top Layer w0.15: R197.1@154.78,4.905 154.78,4.382 D26.1@157.056,2.105
NetD26_2: D26.2 J39.10 | length 25.9
  Top Layer w0.15: J39.10@145.55,22.275 145.55,21.9 146.01,21.44 v1(146.023,21.44) ; D26.2@157.028,3.784 157.028,4.867 157.756,5.595 v1(157.756,7.222)
  Top Layer w0.4: D26.2@157.028,3.784 D26.2@157.056,3.755
  INT2_SIG w0.15: v1(146.023,21.44) 146.023,20.85 145.885,20.711 145.885,18.19 152.815,11.26 155.964,11.26 157.756,9.468 v1(157.756,7.222)
NetD28_1: D28.1 D28.2 Q26.1 R314.1 | length 6.1
  Top Layer w0.25: Q26.1@28.55,162.756 28.6,162.806 D28.1@28.6,165.5 D28.2@30.5,165.5 R314.1@30.5,164.1
NetD28_3: D28.3 U75.3 X114.1 | length 18
  Top Layer w0.15: U75.3@28.475,180.35 28.475,178.962 28.275,178.762 28.275,177.55 28.6,177.225 29.643,177.225 29.886,176.982 29.886,175.768 29.668,175.55 29.449,175.55 29.1,175.201 29.1,171.621 31.096,169.625 X114.1@32.225,169.625
  Top Layer w0.25: D28.3@29.55,167.7 30.3,167.7 X114.1@32.225,169.625
NetD29_1: D29.1 R202.1 | length 2.5
  Top Layer w0.15: R202.1@169.694,107.862 170.391,107.165 D29.1@170.391,105.65
NetD30_1: D30.1 R204.1 | length 3.2
  Top Layer w0.15: R204.1@169.7,106.9 169.7,104.712 D30.1@170.425,103.988
NetD30_2: D30.2 J43.10 | length 21.4
  Top Layer w0.15: J43.10@156.05,107.8 158.441,107.8 159.325,108.684 159.325,110.255 161.398,112.329 164.625,112.329 165.5,111.454 165.5,107.262 D30.2@168.775,103.988
NetD34_1: D34.1 R239.2 | length 37.8
  Top Layer w0.15: v1(29.275,132.722) R239.2@30.036,132.722
  Top Layer w0.25: D34.1@20.425,165.3 v1(21.25,165.3)
  INT2_SIG w0.15: v1(21.25,165.3) 24.126,162.424 24.126,152.734 23.7,152.309 23.7,149.909 29.134,144.475 29.134,132.862 v1(29.275,132.722)
NetD39_1: D39.1 R279.1 | length 3.7
  Top Layer w0.15: R279.1@227.225,43.75 227.225,42.385 227.49,42.12 D39.1@227.49,40.2
NetD39_3: D39.3 Q19.6 | length 7.4
  Top Layer w0.15: Q19.6@225.925,43.925 225.925,42.55 225.14,41.765 225.14,38.15 225.99,37.3 D39.3@225.99,37.2
NetD40_1: D40.1 R280.1 | length 3.6
  Top Layer w0.15: R280.1@223.625,43.7 223.625,42.385 223.89,42.12 D40.1@223.89,40.2
NetD40_3: D40.3 Q19.3 | length 12
  Top Layer w0.15: D40.3@222.39,37.2 222.39,37.3 221.54,38.15 221.54,44.64 222.8,45.9 223.875,45.9 224.5,45.275 Q19.3@224.925,45.275
NetD41_1: D41.1 R281.1 | length 3.5
  Top Layer w0.15: R281.1@220.025,43.6 220.025,42.335 220.24,42.12 D41.1@220.24,40.15
NetD41_3: D41.3 Q18.6 | length 7.8
  Top Layer w0.15: Q18.6@218.61,44.275 218.61,42.51 217.89,41.79 217.89,38.1 218.74,37.25 D41.3@218.74,37.15
NetD42_1: D42.1 R282.1 | length 3.6
  Top Layer w0.15: R282.1@216.425,43.65 216.425,42.335 216.64,42.12 D42.1@216.64,40.15
NetD42_3: D42.3 Q18.3 | length 11.4
  Top Layer w0.15: D42.3@215.14,37.15 215.14,37.25 214.29,38.1 214.29,43.957 216.208,45.875 216.868,45.875 217.118,45.625 Q18.3@217.61,45.625
NetD44_3: D44.3 Q24.1 Q24.3 R335.2 | length 9.4
  Top Layer w0.25: Q24.3@26.13,147.66 D44.3@29.065,147.66 ; D44.3@29.315,147.66 D44.3@29.35,147.625 30.175,147.625
  Top Layer w0.5: Q24.1@26.13,145.12 24.705,145.12 24.407,145.418 24.407,147.367 24.7,147.66 Q24.3@26.13,147.66
NetD45_1: D45.1 R396.1 | length 1.7
  Top Layer w0.4: v1(126.482,195.26) D45.1@126.482,196.15
  Bottom Layer w0.15: R396.1@126.482,194.5 v1(126.482,195.26)
NetD46_1: D46.1 R351.1 | length 1.6
  Top Layer w0.25: R351.1@11.95,174.72 D46.1@13.59,174.72
NetD46_3: D46.3 Q25.3 R9.2 | length 4.4
  Top Layer w0.15: R9.2@9.225,171.565 10.878,171.565 Q25.3@10.88,171.563 10.887,171.57 D46.3@13.59,171.57
NetD48_1: D48.1 R430.1 | length 130
  Top Layer w0.15: v1(29.705,68.248) R430.1@29.705,68.988
  Top Layer w0.25: D48.1@20.4,178.75 20.993,178.157 21.499,178.157 v1(21.566,178.09)
  INT2_SIG w0.15: v1(21.566,178.09) 21.566,177.462 21.748,177.279 21.748,176.773 20.122,175.146 20.122,174.457 19.25,173.585 18.71,173.585 17.326,172.201 17.326,168.932 18.326,167.932 18.943,167.932 20.576,166.299 20.576,165.149 23.826,161.899 23.826,152.859 23.4,152.433 23.4,149.785 28.7,144.485 28.7,132.13 36.484,124.346 36.484,121.316 37.919,119.881 37.919,115.532 38.8,114.651 38.8,87.289 31.963,80.452 30.1,80.452 28.75,79.102 28.75,76.271 30.35,74.671 30.35,68.893 v1(29.705,68.248)
NetD49_1: D49.1 R431.1 | length 40.6
  Top Layer w0.15: R431.1@18.465,145.105 18.475,145.115 v1(18.475,145.87)
  Top Layer w0.25: D49.1@20.4,177.05 v1(21.223,177.05)
  INT2_SIG w0.15: v1(18.475,145.87) 23.1,150.495 23.1,152.557 23.526,152.983 23.526,161.509 20.09,164.945 20.09,166.29 18.855,167.525 18.17,167.525 16.944,168.75 16.944,174.235 18.196,175.487 19.66,175.487 v1(21.223,177.05)
NetJ1_1: J1.1 J1A.1 RA16.5 | length 71.1
  Bottom Layer w0.15: J1.1@60.3,59.02 64.05,59.02 J1A.1@65.38,59.02 66.02,59.02 83.591,59.02 91.386,66.815 120.363,66.815 124.496,70.949 RA16.5@124.496,72.872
